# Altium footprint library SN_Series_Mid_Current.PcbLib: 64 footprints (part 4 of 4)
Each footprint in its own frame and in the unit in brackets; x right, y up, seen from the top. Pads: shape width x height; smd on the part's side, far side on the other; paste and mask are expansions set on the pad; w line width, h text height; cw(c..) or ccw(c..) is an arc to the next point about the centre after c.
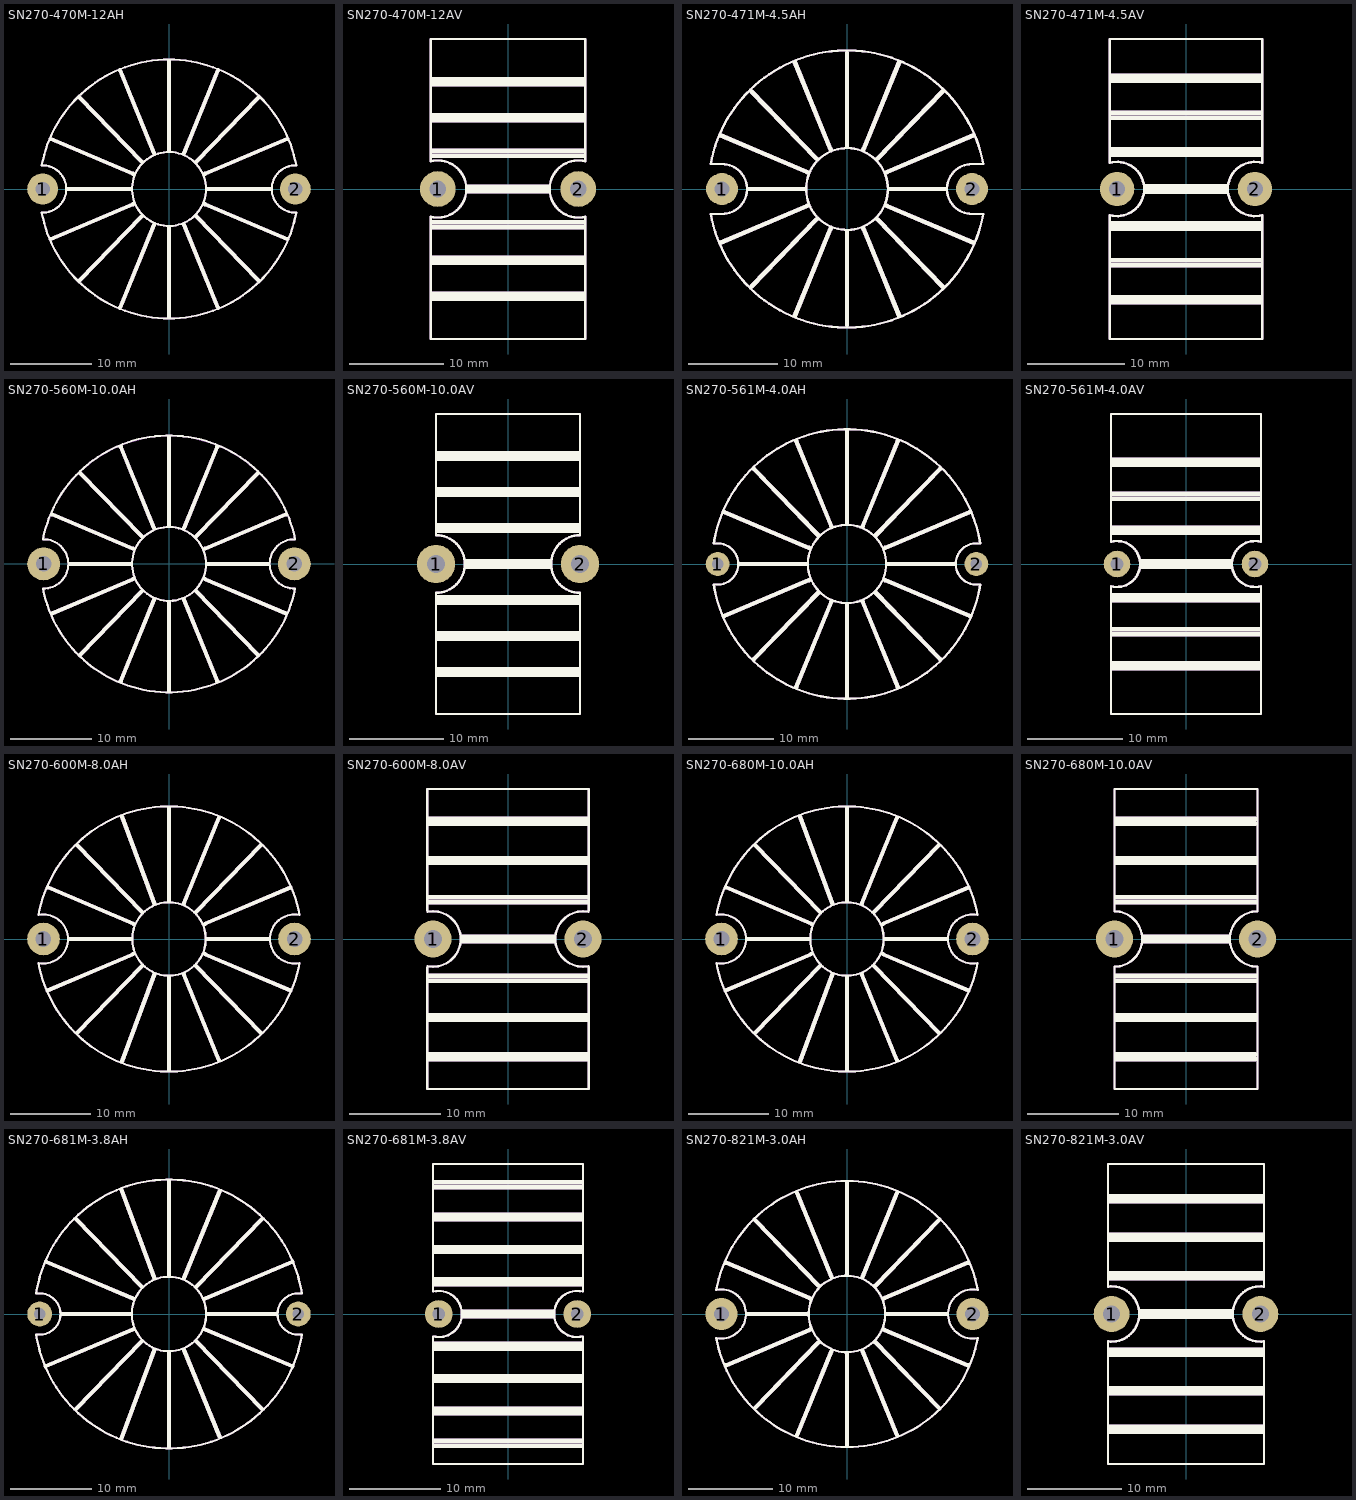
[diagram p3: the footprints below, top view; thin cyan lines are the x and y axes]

## SN270-470M-12AH [mil]
pads (2):
  round 150 hole 70: 1(-615,0) 2(615,0)
Top Overlay:
  circle w10: c0,0 r180
  lines w10: -619.39,-115.15 ccw(c0,0) 619.39,-115.12 ; -619.39,115.15 cw(c0,0) 619.39,115.15 ; -618.33,-114.95 ccw(c-615,0) -618.33,114.95 ; 618.33,114.95 ccw(c615,0) 618.49,-114.95
  lines w19.68: -575.83,-244 -175.3,-74.28 ; -575.83,244 -175.3,74.28 ; -495,0 -185,0 ; -435.29,-444.82 -132.5,-132.5 ; -435.29,444.82 -132.5,132.5 ; -237.42,-576.5 -72.46,-173.99 ; -237.42,576.5 -72.46,173.99 ; 0,-620 0,-185 ; 0,185 0,620 ; 72.46,-173.99 237.42,-576.5 ; 72.46,173.99 237.42,576.5 ; 132.5,-132.5 435.29,-444.82 ; 132.5,132.5 435.29,444.82 ; 175.3,-74.28 575.83,-244 ; 175.3,74.28 575.83,244 ; 185,0 495,0
Mechanical 29:
  circle w10: c0,0 r180
  lines w10: -619.39,-115.15 ccw(c0,0) 619.39,-115.12 ; -619.39,115.15 cw(c0,0) 619.39,115.15 ; -618.33,-114.95 ccw(c-615,0) -618.33,114.95 ; 618.33,114.95 ccw(c615,0) 618.49,-114.95
  lines w19.68: -575.83,-244 -175.3,-74.28 ; -575.83,244 -175.3,74.28 ; -495,0 -185,0 ; -435.29,-444.82 -132.5,-132.5 ; -435.29,444.82 -132.5,132.5 ; -237.42,-576.5 -72.46,-173.99 ; -237.42,576.5 -72.46,173.99 ; 0,-620 0,-185 ; 0,185 0,620 ; 72.46,-173.99 237.42,-576.5 ; 72.46,173.99 237.42,576.5 ; 132.5,-132.5 435.29,-444.82 ; 132.5,132.5 435.29,444.82 ; 175.3,-74.28 575.83,-244 ; 175.3,74.28 575.83,244 ; 185,0 495,0
  text "'.Designator'" at -290,145.15 h400

## SN270-470M-12AV [mil]
pads (2):
  round 150 hole 70: 1(-295,0) 2(295,0)
Top Overlay:
  lines w10: 325,-116.19 cw(c295,0) 325,116.19 ; 325,-116 325,-630 -325,-630 -325,-116.19 ccw(c-295,0) -325,116.19 -325,630 325,630 325,116
  lines w19.68: -320,-460 320,-460 ; -320,-440 320,-440 ; -320,-310 320,-310 ; -320,-290 320,-290 ; -320,-160 320,-160 ; -320,-140 320,-140 ; -320,140 320,140 ; -320,160 320,160 ; -320,290 320,290 ; -320,310 320,310 ; -320,440 320,440 ; -320,460 320,460 ; -170,-10 170,-10 ; -170,10 170,10
Mechanical 29:
  lines w10: 325,-116.19 cw(c295,0) 325,116.19 ; 325,-116 325,-630 -325,-630 -325,-116.19 ccw(c-295,0) -325,116.19 -325,630 325,630 325,116
  lines w19.68: -320,-460 320,-460 ; -320,-440 320,-440 ; -320,-310 320,-310 ; -320,-290 320,-290 ; -320,-160 320,-160 ; -320,-140 320,-140 ; -320,140 320,140 ; -320,160 320,160 ; -320,290 320,290 ; -320,310 320,310 ; -320,440 320,440 ; -320,460 320,460 ; -170,-10 170,-10 ; -170,10 170,10
  text "'.Designator'" at -1750,-64.85 h400

## SN270-471M-4.5AH [mil]
pads (2):
  round 140 hole 65: 1(-550,0) 2(550,0)
Top Overlay:
  circle w10: c0,0 r180
  lines w10: -599.99,-110.03 ccw(c0,0) 599.83,-110.9 ; -599.99,110.03 cw(c0,0) 599.84,110.89 ; -599.83,-110 -550,-110 ccw(c-550,0) -550,110 -599.84,110 ; 599.83,-110 550,-110 cw(c550,0) 550,110 599.84,110
  lines w19.68: -557.42,-236.19 -175.3,-74.28 ; -557.42,236.19 -175.3,74.28 ; -435,0 -185,0 ; -421.36,-430.46 -132.5,-132.5 ; -421.36,430.46 -132.5,132.5 ; -229.83,-557.99 -72.46,-173.99 ; -229.83,557.99 -72.46,173.99 ; 0,-600 0,-185 ; 0,185 0,600 ; 72.46,-173.99 229.83,-557.99 ; 72.46,173.99 229.83,557.99 ; 132.5,-132.5 421.36,-430.46 ; 132.5,132.5 421.36,430.46 ; 175.3,-74.28 557.42,-236.19 ; 175.3,74.28 557.42,236.19 ; 185,0 435,0
Mechanical 29:
  circle w10: c0,0 r180
  lines w10: -599.99,-110.03 ccw(c0,0) 599.83,-110.9 ; -599.99,110.03 cw(c0,0) 599.84,110.89 ; -599.83,-110 -550,-110 ccw(c-550,0) -550,110 -599.84,110 ; 599.83,-110 550,-110 cw(c550,0) 550,110 599.84,110
  lines w19.68: -557.42,-236.19 -175.3,-74.28 ; -557.42,236.19 -175.3,74.28 ; -435,0 -185,0 ; -421.36,-430.46 -132.5,-132.5 ; -421.36,430.46 -132.5,132.5 ; -229.83,-557.99 -72.46,-173.99 ; -229.83,557.99 -72.46,173.99 ; 0,-600 0,-185 ; 0,185 0,600 ; 72.46,-173.99 229.83,-557.99 ; 72.46,173.99 229.83,557.99 ; 132.5,-132.5 421.36,-430.46 ; 132.5,132.5 421.36,430.46 ; 175.3,-74.28 557.42,-236.19 ; 175.3,74.28 557.42,236.19 ; 185,0 435,0
  text "'.Designator'" at -290,145.15 h400

## SN270-471M-4.5AV [mil]
pads (2):
  round 140 hole 65: 1(-280,0) 2(280,0)
Top Overlay:
  lines w10: -310,-106.57 -310,-610 310,-610 310,-106.25 ; -310,106.55 -310,610 310,610 310,106.28 ; -309.81,-105.88 ccw(c-280,0) -309.81,105.88 ; 309.89,-105.86 cw(c280,0) 309.88,105.86
  lines w19.68: -305,-460 305,-460 ; -305,-440 305,-440 ; -305,-310 302,-310 ; -305,-290 305,-290 ; -305,-160 303,-160 ; -305,-140 303,-140 ; -305,140 303,140 ; -305,160 303,160 ; -305,290 305,290 ; -305,310 302,310 ; -305,440 305,440 ; -305,460 305,460 ; -165,-10 165,-10 ; -165,10 165,10
Mechanical 29:
  lines w10: -310,-106.57 -310,-610 310,-610 310,-106.25 ; -310,106.55 -310,610 310,610 310,106.28 ; -309.81,-105.88 ccw(c-280,0) -309.81,105.88 ; 309.89,-105.86 cw(c280,0) 309.88,105.86
  lines w19.68: -305,-460 305,-460 ; -305,-440 305,-440 ; -305,-310 302,-310 ; -305,-290 305,-290 ; -305,-160 303,-160 ; -305,-140 303,-140 ; -305,140 303,140 ; -305,160 303,160 ; -305,290 305,290 ; -305,310 302,310 ; -305,440 305,440 ; -305,460 305,460 ; -165,-10 165,-10 ; -165,10 165,10
  text "'.Designator'" at -1750,-64.85 h400

## SN270-560M-10.0AH [mil]
pads (2):
  round 160 hole 76: 1(-610,0) 2(610,0)
Top Overlay:
  circle w10: c0,0 r180
  lines w10: -613.23,119.96 cw(c-610,0) -613.38,-119.95 ccw(c0,0) 613.38,-119.95 cw(c610,0) 613.23,119.96 ; -613.25,120.64 cw(c0,0) 613.25,120.64
  lines w19.68: -569.45,-241.29 -175.3,-74.28 ; -569.45,241.29 -175.3,74.28 ; -485,0 -185,0 ; -430.31,-439.69 -132.5,-132.5 ; -430.31,439.69 -132.5,132.5 ; -234.79,-570.09 -72.46,-173.99 ; -234.79,570.09 -72.46,173.99 ; 0,-615 0,-185 ; 0,185 0,615 ; 72.46,-173.99 234.79,-570.09 ; 72.46,173.99 234.79,570.09 ; 132.5,-132.5 430.31,-439.69 ; 132.5,132.5 430.31,439.69 ; 175.3,-74.28 569.45,-241.29 ; 175.3,74.28 569.45,241.29 ; 185,0 485,0
Mechanical 29:
  circle w10: c0,0 r180
  lines w10: -613.38,-119.95 ccw(c0,0) 613.38,-119.95 cw(c610,0) 613.23,119.96 ccw(c0.02,-0.68) -613.23,119.96 cw(c-610,0) -613.38,-119.95
  lines w19.68: -569.45,-241.29 -175.3,-74.28 ; -569.45,241.29 -175.3,74.28 ; -485,0 -185,0 ; -430.31,-439.69 -132.5,-132.5 ; -430.31,439.69 -132.5,132.5 ; -234.79,-570.09 -72.46,-173.99 ; -234.79,570.09 -72.46,173.99 ; 0,-615 0,-185 ; 0,185 0,615 ; 72.46,-173.99 234.79,-570.09 ; 72.46,173.99 234.79,570.09 ; 132.5,-132.5 430.31,-439.69 ; 132.5,132.5 430.31,439.69 ; 175.3,-74.28 569.45,-241.29 ; 175.3,74.28 569.45,241.29 ; 185,0 485,0
  text "'.Designator'" at -290,145.15 h400

## SN270-560M-10.0AV [mil]
pads (2):
  round 160 hole 76: 1(-300,0) 2(300,0)
Top Overlay:
  lines w10: -300,-625 -300,-120 ccw(c-300,0) -300,120 -300,625 300,625 300,120 ccw(c300,0) 300,-120 300,-625 -300,-625
  lines w19.68: -295,-460 295,-460 ; -295,-440 295,-440 ; -295,-310 295,-310 ; -295,-290 295,-290 ; -295,-160 295,-160 ; -295,-140 295,-140 ; -295,140 295,140 ; -295,160 295,160 ; -295,290 295,290 ; -295,310 295,310 ; -295,440 295,440 ; -295,460 295,460 ; -175,-10 175,-10 ; -175,10 175,10
Mechanical 29:
  lines w10: -300,-625 -300,-120 ccw(c-300,0) -300,120 -300,625 300,625 300,120 ccw(c300,0) 300,-120 300,-625 -300,-625
  lines w19.68: -295,-460 295,-460 ; -295,-440 295,-440 ; -295,-310 295,-310 ; -295,-290 295,-290 ; -295,-160 295,-160 ; -295,-140 295,-140 ; -295,140 295,140 ; -295,160 295,160 ; -295,290 295,290 ; -295,310 295,310 ; -295,440 295,440 ; -295,460 295,460 ; -175,-10 175,-10 ; -175,10 175,10
  text "'.Designator'" at -1750,-64.85 h400

## SN270-561M-4.0AH [mil]
pads (2):
  round 110 hole 53: 1(-595,0) 2(595,0)
Top Overlay:
  circle w10: c0,0 r180
  lines w10: -612.83,-94.01 ccw(c0,0) 612.83,-94.01 ; -612.83,94.01 cw(c0,0) 612.86,93.84 ; -610.72,-93.69 ccw(c-595,0) -610.72,93.69 ; 610.72,-93.69 cw(c595,0) 611.27,93.6
  lines w19.68: -566.62,-240.1 -175.3,-74.28 ; -566.62,240.1 -175.3,74.28 ; -495,0 -185,0 ; -428.33,-437.64 -132.5,-132.5 ; -428.33,437.64 -132.5,132.5 ; -233.63,-567.25 -72.46,-173.99 ; -233.63,567.25 -72.46,173.99 ; 0,-610 0,-185 ; 0,185 0,610 ; 72.46,-173.99 233.63,-567.25 ; 72.46,173.99 233.63,567.25 ; 132.5,-132.5 428.33,-437.64 ; 132.5,132.5 428.33,437.64 ; 175.3,-74.28 566.62,-240.1 ; 175.3,74.28 566.62,240.1 ; 185,0 495,0
Mechanical 29:
  circle w10: c0,0 r180
  lines w10: -612.83,-94.01 ccw(c0,0) 612.83,-94.01 ; -612.83,94.01 cw(c0,0) 612.86,93.84 ; -610.72,-93.69 ccw(c-595,0) -610.72,93.69 ; 610.72,-93.69 cw(c595,0) 611.27,93.6
  lines w19.68: -566.62,-240.1 -175.3,-74.28 ; -566.62,240.1 -175.3,74.28 ; -495,0 -185,0 ; -428.33,-437.64 -132.5,-132.5 ; -428.33,437.64 -132.5,132.5 ; -233.63,-567.25 -72.46,-173.99 ; -233.63,567.25 -72.46,173.99 ; 0,-610 0,-185 ; 0,185 0,610 ; 72.46,-173.99 233.63,-567.25 ; 72.46,173.99 233.63,567.25 ; 132.5,-132.5 428.33,-437.64 ; 132.5,132.5 428.33,437.64 ; 175.3,-74.28 566.62,-240.1 ; 175.3,74.28 566.62,240.1 ; 185,0 495,0
  text "'.Designator'" at -290,145.15 h400

## SN270-561M-4.0AV [mil]
pads (2):
  round 110 hole 53: 1(-285,0) 2(285,0)
Top Overlay:
  lines w10: -310,-92.28 -310,-620 310,-620 310,-92.28 ; -310,92.42 -310,620 310,620 310,92.42 ; -309.84,-91.69 ccw(c-285,0) -309.81,91.7 ; 309.81,91.7 ccw(c285,0) 309.84,-91.69
  lines w19.68: -305,-430 303,-430 ; -305,-410 303,-410 ; -305,-290 303,-290 ; -305,-270 303,-270 ; -305,-150 303,-150 ; -305,-130 303,-130 ; -305,130 303,130 ; -305,150 303,150 ; -305,270 303,270 ; -305,290 303,290 ; -305,410 303,410 ; -305,430 303,430 ; -185,-10 185,-10 ; -185,10 185,10
Mechanical 29:
  lines w10: -310,-92.28 -310,-620 310,-620 310,-92.28 ; -310,92.42 -310,620 310,620 310,92.42 ; -309.84,-91.69 ccw(c-285,0) -309.81,91.7 ; 309.81,91.7 ccw(c285,0) 309.84,-91.69
  lines w19.68: -305,-430 303,-430 ; -305,-410 303,-410 ; -305,-290 303,-290 ; -305,-270 303,-270 ; -305,-150 303,-150 ; -305,-130 303,-130 ; -305,130 303,130 ; -305,150 303,150 ; -305,270 303,270 ; -305,290 303,290 ; -305,410 303,410 ; -305,430 303,430 ; -185,-10 185,-10 ; -185,10 185,10
  text "'.Designator'" at -1750,-64.85 h400

## SN270-600M-8.0AH [mil]
pads (2):
  round 160 hole 76: 1(-615,0) 2(615,0)
Top Overlay:
  circle w10: c0,0 r180
  lines w10: 638.67,-117.64 cw(c615,0) 638.67,117.64 ; 639.25,-117.75 cw(c0,0) -639.29,-117.52 ccw(c-615,0) -639.29,117.52 cw(c0,0) 639.25,117.75
  lines w19.68: -596.03,-252.56 -175.3,-74.28 ; -593.79,252.95 -173.05,74.68 ; -490,0 -185,0 ; -450,-460 -132.7,-132.43 ; -450,460 -132.7,132.43 ; -230,-600 -70.44,-171.87 ; -230,600 -70.44,171.87 ; 0,-640 0,-185 ; 0,185 0,640 ; 72.46,-173.99 243.97,-592.47 ; 72.46,173.99 243.97,592.47 ; 132.5,-132.5 450,-460 ; 132.5,132.5 450,460 ; 175.3,-74.28 596.03,-252.56 ; 175.3,74.28 596.03,252.56 ; 185,0 490,0
Mechanical 29:
  circle w10: c0,0 r180
  lines w10: 638.67,-117.64 cw(c615,0) 638.67,117.64 ; 639.25,-117.75 cw(c0,0) -639.29,-117.52 ccw(c-615,0) -639.29,117.52 cw(c0,0) 639.25,117.75
  lines w19.68: -596.03,-252.56 -175.3,-74.28 ; -593.79,252.95 -173.05,74.68 ; -490,0 -185,0 ; -450,-460 -132.7,-132.43 ; -450,460 -132.7,132.43 ; -230,-600 -70.44,-171.87 ; -230,600 -70.44,171.87 ; 0,-640 0,-185 ; 0,185 0,640 ; 72.46,-173.99 243.97,-592.47 ; 72.46,173.99 243.97,592.47 ; 132.5,-132.5 450,-460 ; 132.5,132.5 450,460 ; 175.3,-74.28 596.03,-252.56 ; 175.3,74.28 596.03,252.56 ; 185,0 490,0
  text "'.Designator'" at -290,145.15 h400

## SN270-600M-8.0AV [mil]
pads (2):
  round 160 hole 76: 1(-325,0) 2(325,0)
Top Overlay:
  lines w10: -350,-125 -350,-650 350,-650 350,-122.57 ; -350,125 -350,650 350,650 350,125 ; -348.53,-117.67 ccw(c-325,0) -348.53,117.67 ; 348.53,-117.67 cw(c325,0) 348.53,117.67
  lines w19.68: -345,-520 345,-520 ; -345,-500 345,-500 ; -345,-350 345,-350 ; -345,-330 345,-330 ; -345,-180 345,-180 ; -345,-160 345,-160 ; -345,160 345,160 ; -345,180 345,180 ; -345,330 345,330 ; -345,350 345,350 ; -345,500 345,500 ; -345,520 345,520 ; -200,-10 200,-10 ; -200,10 200,10
Mechanical 29:
  lines w10: -350,-125 -350,-650 350,-650 350,-122.57 ; -350,125 -350,650 350,650 350,125 ; -348.53,-117.67 ccw(c-325,0) -348.53,117.67 ; 348.53,-117.67 cw(c325,0) 348.53,117.67
  lines w19.68: -345,-520 345,-520 ; -345,-500 345,-500 ; -345,-350 345,-350 ; -345,-330 345,-330 ; -345,-180 345,-180 ; -345,-160 345,-160 ; -345,160 345,160 ; -345,180 345,180 ; -345,330 345,330 ; -345,350 345,350 ; -345,500 345,500 ; -345,520 345,520 ; -200,-10 200,-10 ; -200,10 200,10
  text "'.Designator'" at -1750,-64.85 h400

## SN270-680M-10.0AH [mil]
pads (2):
  round 160 hole 77: 1(-615,0) 2(615,0)
Top Overlay:
  circle w10: c0,0 r180
  lines w10: 638.67,-117.64 cw(c615,0) 638.67,117.64 ; 639.25,-117.75 cw(c0,0) -639.29,-117.52 ccw(c-615,0) -639.29,117.52 cw(c0,0) 639.25,117.75
  lines w19.68: -596.03,-252.56 -175.3,-74.28 ; -593.79,252.95 -173.05,74.68 ; -490,0 -185,0 ; -450,-460 -132.7,-132.43 ; -450,460 -132.7,132.43 ; -230,-600 -70.44,-171.87 ; -230,600 -70.44,171.87 ; 0,-640 0,-185 ; 0,185 0,640 ; 72.46,-173.99 243.97,-592.47 ; 72.46,173.99 243.97,592.47 ; 132.5,-132.5 450,-460 ; 132.5,132.5 450,460 ; 175.3,-74.28 596.03,-252.56 ; 175.3,74.28 596.03,252.56 ; 185,0 490,0
Mechanical 29:
  circle w10: c0,0 r180
  lines w10: 638.67,-117.64 cw(c615,0) 638.67,117.64 ; 639.25,-117.75 cw(c0,0) -639.29,-117.52 ccw(c-615,0) -639.29,117.52 cw(c0,0) 639.25,117.75
  lines w19.68: -596.03,-252.56 -175.3,-74.28 ; -593.79,252.95 -173.05,74.68 ; -490,0 -185,0 ; -450,-460 -132.7,-132.43 ; -450,460 -132.7,132.43 ; -230,-600 -70.44,-171.87 ; -230,600 -70.44,171.87 ; 0,-640 0,-185 ; 0,185 0,640 ; 72.46,-173.99 243.97,-592.47 ; 72.46,173.99 243.97,592.47 ; 132.5,-132.5 450,-460 ; 132.5,132.5 450,460 ; 175.3,-74.28 596.03,-252.56 ; 175.3,74.28 596.03,252.56 ; 185,0 490,0
  text "'.Designator'" at -290,145.15 h400

## SN270-680M-10.0AV [mil]
pads (2):
  round 160 hole 77: 1(-310,0) 2(310,0)
Top Overlay:
  lines w10: -310,-650 -310,-120 ccw(c-310,0) -310,120 -310,650 310,650 310,120 ccw(c310,0) 310,-120 310,-650 -310,-650
  lines w19.68: -305,-520 301,-520 ; -305,-500 301,-500 ; -305,-350 302,-350 ; -305,-330 302,-330 ; -305,-180 303,-180 ; -305,-160 303,-160 ; -305,160 303,160 ; -305,180 303,180 ; -305,330 302,330 ; -305,350 302,350 ; -305,500 301,500 ; -305,520 301,520 ; -185,-10 185,-10 ; -185,10 185,10
Mechanical 29:
  lines w10: -310,-650 -310,-120 ccw(c-310,0) -310,120 -310,650 310,650 310,120 ccw(c310,0) 310,-120 310,-650 -310,-650
  lines w19.68: -305,-520 301,-520 ; -305,-500 301,-500 ; -305,-350 302,-350 ; -305,-330 302,-330 ; -305,-180 303,-180 ; -305,-160 303,-160 ; -305,160 303,160 ; -305,180 303,180 ; -305,330 302,330 ; -305,350 302,350 ; -305,500 301,500 ; -305,520 301,520 ; -185,-10 185,-10 ; -185,10 185,10
  text "'.Designator'" at -1750,-64.85 h400

## SN270-681M-3.8AH [mil]
pads (2):
  round 120 hole 56: 1(-625,0) 2(625,0)
Top Overlay:
  circle w10: c0,0 r180
  lines w10: -642.42,-98.97 ccw(c0,0) 642.42,-98.97 ; -642.42,98.97 cw(c0,0) 642.42,98.97 ; -640.89,-98.73 ccw(c-625,0) -640.89,98.73 ; 640.89,-98.73 cw(c625,0) 640.89,98.73
  lines w19.68: -596.03,-252.56 -175.3,-74.28 ; -593.79,252.95 -173.05,74.68 ; -515,0 -185,0 ; -450,-460 -132.7,-132.43 ; -450,460 -132.7,132.43 ; -230,-600 -70.44,-171.87 ; -230,600 -70.44,171.87 ; 0,-640 0,-185 ; 0,185 0,640 ; 72.46,-173.99 243.97,-592.47 ; 72.46,173.99 243.97,592.47 ; 132.5,-132.5 450,-460 ; 132.5,132.5 450,460 ; 175.3,-74.28 596.03,-252.56 ; 175.3,74.28 596.03,252.56 ; 185,0 515,0
Mechanical 29:
  circle w10: c0,0 r180
  lines w10: -642.42,-98.97 ccw(c0,0) 642.42,-98.97 ; -642.42,98.97 cw(c0,0) 642.42,98.97 ; -640.89,-98.73 ccw(c-625,0) -640.89,98.73 ; 640.89,-98.73 cw(c625,0) 640.89,98.73
  lines w19.68: -596.03,-252.56 -175.3,-74.28 ; -593.79,252.95 -173.05,74.68 ; -515,0 -185,0 ; -450,-460 -132.7,-132.43 ; -450,460 -132.7,132.43 ; -230,-600 -70.44,-171.87 ; -230,600 -70.44,171.87 ; 0,-640 0,-185 ; 0,185 0,640 ; 72.46,-173.99 243.97,-592.47 ; 72.46,173.99 243.97,592.47 ; 132.5,-132.5 450,-460 ; 132.5,132.5 450,460 ; 175.3,-74.28 596.03,-252.56 ; 175.3,74.28 596.03,252.56 ; 185,0 515,0
  text "'.Designator'" at -290,145.15 h400

## SN270-681M-3.8AV [mil]
pads (2):
  round 120 hole 56: 1(-300,0) 2(300,0)
Top Overlay:
  lines w10: -325,-97.13 -325,-650 325,-650 325,-97.13 ; -325,97.28 -325,650 325,650 325,97.28 ; -323.77,-97.13 ccw(c-300,0) -323.16,97.28 ; 323.16,97.28 ccw(c300,0) 323.77,-97.13
  lines w19.68: -320,-570 320,-570 ; -320,-550 320,-550 ; -320,-430 320,-430 ; -320,-410 320,-410 ; -320,-290 320,-290 ; -320,-270 320,-270 ; -320,-150 320,-150 ; -320,-130 320,-130 ; -320,130 320,130 ; -320,150 320,150 ; -320,270 320,270 ; -320,290 320,290 ; -320,410 320,410 ; -320,430 320,430 ; -320,550 320,550 ; -320,570 320,570 ; -195,-10 195,-10 ; -195,10 195,10
Mechanical 29:
  lines w10: -325,-97.13 -325,-650 325,-650 325,-97.13 ; -325,97.28 -325,650 325,650 325,97.28 ; -323.77,-97.13 ccw(c-300,0) -323.16,97.28 ; 323.16,97.28 ccw(c300,0) 323.77,-97.13
  lines w19.68: -320,-570 320,-570 ; -320,-550 320,-550 ; -320,-430 320,-430 ; -320,-410 320,-410 ; -320,-290 320,-290 ; -320,-270 320,-270 ; -320,-150 320,-150 ; -320,-130 320,-130 ; -320,130 320,130 ; -320,150 320,150 ; -320,270 320,270 ; -320,290 320,290 ; -320,410 320,410 ; -320,430 320,430 ; -320,550 320,550 ; -320,570 320,570 ; -195,-10 195,-10 ; -195,10 195,10
  text "'.Designator'" at -1750,-64.85 h400

## SN270-821M-3.0AH [mil]
pads (2):
  round 150 hole 70: 1(-590,0) 2(590,0)
Top Overlay:
  circle w10: c0,0 r180
  lines w10: -614.73,-112.81 ccw(c0,0) 614.69,-113.05 ; -614.69,113.05 cw(c0,0) 614.69,113.05 ; -613.46,-112.58 ccw(c-590,0) -612.84,112.71 ; 612.84,-112.71 cw(c590,0) 612.84,112.71
  lines w19.68: -569.45,-241.29 -175.3,-74.28 ; -569.45,241.29 -175.3,74.28 ; -470,0 -185,0 ; -430.31,-439.69 -132.5,-132.5 ; -430.31,439.69 -132.5,132.5 ; -234.79,-570.09 -72.46,-173.99 ; -234.79,570.09 -72.46,173.99 ; 0,-615 0,-185 ; 0,185 0,615 ; 72.46,-173.99 234.79,-570.09 ; 72.46,173.99 234.79,570.09 ; 132.5,-132.5 430.31,-439.69 ; 132.5,132.5 430.31,439.69 ; 175.3,-74.28 569.45,-241.29 ; 175.3,74.28 569.45,241.29 ; 185,0 470,0
Mechanical 29:
  circle w10: c0,0 r180
  lines w10: -614.73,-112.81 ccw(c0,0) 614.69,-113.05 ; -614.69,113.05 cw(c0,0) 614.69,113.05 ; -613.46,-112.58 ccw(c-590,0) -612.84,112.71 ; 612.84,-112.71 cw(c590,0) 612.84,112.71
  lines w19.68: -569.45,-241.29 -175.3,-74.28 ; -569.45,241.29 -175.3,74.28 ; -470,0 -185,0 ; -430.31,-439.69 -132.5,-132.5 ; -430.31,439.69 -132.5,132.5 ; -234.79,-570.09 -72.46,-173.99 ; -234.79,570.09 -72.46,173.99 ; 0,-615 0,-185 ; 0,185 0,615 ; 72.46,-173.99 234.79,-570.09 ; 72.46,173.99 234.79,570.09 ; 132.5,-132.5 430.31,-439.69 ; 132.5,132.5 430.31,439.69 ; 175.3,-74.28 569.45,-241.29 ; 175.3,74.28 569.45,241.29 ; 185,0 470,0
  text "'.Designator'" at -290,145.15 h400

## SN270-821M-3.0AV [mil]
pads (2):
  round 150 hole 70: 1(-310,0) 2(310,0)
Top Overlay:
  lines w10: -325,-114.11 -325,-625 325,-625 325,-114.11 ; -325,114.11 -325,625 325,625 325,114.11 ; -324.26,-114.11 ccw(c-310,0) -324.26,114.11 ; 324.26,-114.11 cw(c310,0) 324.26,114.11
  lines w19.68: -320,-490 320,-490 ; -320,-470 320,-470 ; -320,-330 320,-330 ; -320,-310 320,-310 ; -320,-170 320,-170 ; -320,-150 320,-150 ; -320,150 320,150 ; -320,170 320,170 ; -320,310 320,310 ; -320,330 320,330 ; -320,470 320,470 ; -320,490 320,490 ; -190,-10 190,-10 ; -190,10 190,10
Mechanical 29:
  lines w10: -325,-114.11 -325,-625 325,-625 325,-114.11 ; -325,114.11 -325,625 325,625 325,114.11 ; -324.26,-114.11 ccw(c-310,0) -324.26,114.11 ; 324.26,-114.11 cw(c310,0) 324.26,114.11
  lines w19.68: -320,-490 320,-490 ; -320,-470 320,-470 ; -320,-330 320,-330 ; -320,-310 320,-310 ; -320,-170 320,-170 ; -320,-150 320,-150 ; -320,150 320,150 ; -320,170 320,170 ; -320,310 320,310 ; -320,330 320,330 ; -320,470 320,470 ; -320,490 320,490 ; -190,-10 190,-10 ; -190,10 190,10
  text "'.Designator'" at -1750,-64.85 h400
